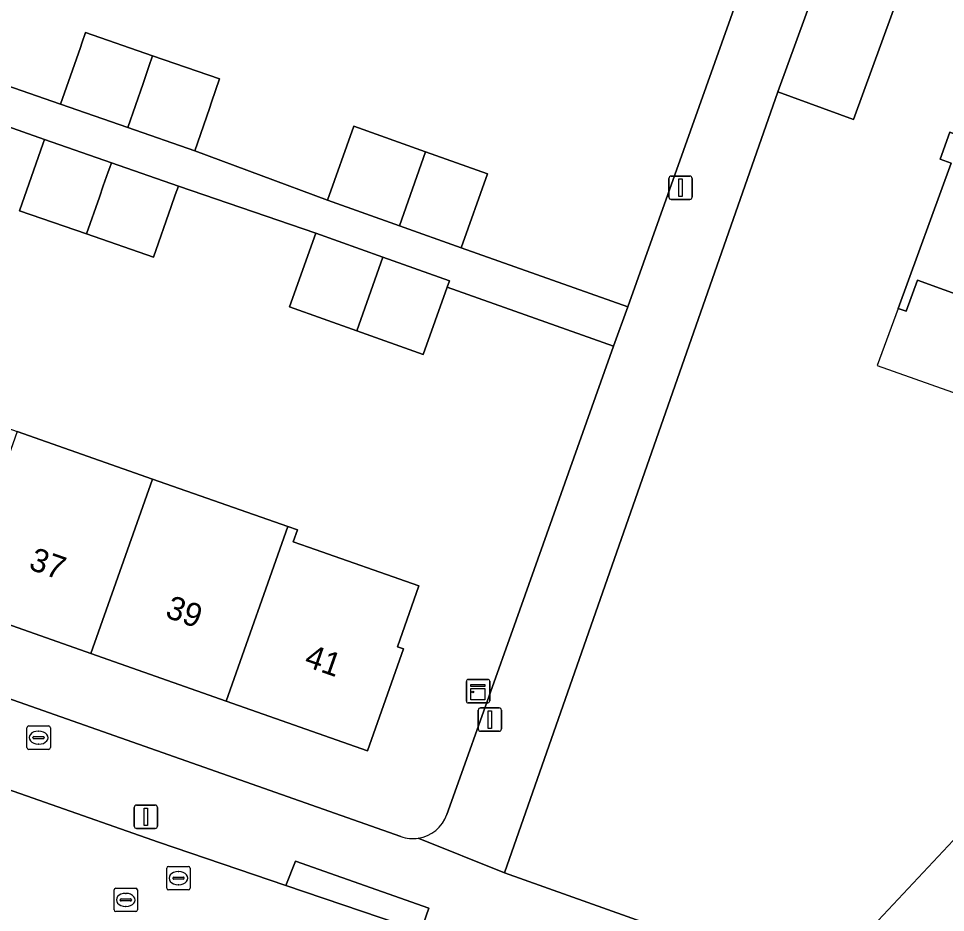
# Model space of a CAD drawing. Extents: x 163266 to 164362, y 381528 to 382286.
# Drawn here: x 163804.78 to 163844.41, y 381775.16 to 381813.39 of the extents above; entities that cross this region are included whole.
import ezdxf

# ---------------------------------------------------------------- set-up
doc = ezdxf.new("R2010")
doc.units = 0
for name, color, linetype in [('IMGEO_Brandkraan', 7, 'Continuous'), ('IMGEO_Erf', 7, 'Continuous'), ('IMGEO_Groenvoorziening', 7, 'Continuous'), ('IMGEO_Kast', 7, 'Continuous'), ('IMGEO_Lichtmast', 7, 'Continuous'), ('IMGEO_Pand', 7, 'Continuous'), ('IMGEO_Pand_nummerreeks', 7, 'Continuous'), ('IMGEO_Pand_overbouw', 7, 'Continuous'), ('IMGEO_Rijbaan_lokaal_open', 7, 'Continuous'), ('IMGEO_Rioolput', 7, 'Continuous'), ('IMGEO_Voetpad_open', 7, 'Continuous')]:
    doc.layers.add(name, color=color, linetype=linetype)

msp = doc.modelspace()

# ---------------------------------------------------------------- linework, layer by layer
at = {"layer": 'IMGEO_Brandkraan'}
for p, q in [((163805.142, 381782.214), (163805.142, 381783.066)), ((163805.217, 381783.14), (163806.069, 381783.14)), ((163805.63, 381782.92), (163805.655, 381782.92)), ((163806.143, 381783.066), (163806.143, 381782.214)), ((163805.401, 381782.634), (163805.401, 381782.646)), ((163805.839, 381782.597), (163805.441, 381782.597)), ((163805.444, 381782.683), (163805.842, 381782.683)), ((163805.885, 381782.646), (163805.885, 381782.634)), ((163806.069, 381782.14), (163805.217, 381782.14)), ((163805.653, 381782.36), (163805.628, 381782.36))]:
    msp.add_line(p, q, dxfattribs=at)
for points in [[(163805.142, 381782.214), (163805.142, 381783.066)], [(163805.217, 381783.14), (163806.069, 381783.14)], [(163806.143, 381783.066), (163806.143, 381782.214)], [(163806.069, 381782.14), (163805.217, 381782.14)]]:
    msp.add_lwpolyline(points, dxfattribs=at)
for centre, radius, start, end in [((163805.219, 381783.064), 0.0765, 91.552, 178.448), ((163805.219, 381783.064), 0.0765, 91.552, 178.448), ((163806.067, 381783.064), 0.0765, 1.552, 88.448), ((163806.067, 381783.064), 0.0765, 1.552, 88.448), ((163805.441, 381782.643), 0.0403, 85.8775, 175.7526), ((163805.438, 381782.633), 0.0366, 178.938, 274.7102), ((163805.842, 381782.64), 0.043, 264.8664, 352.4533), ((163805.846, 381782.645), 0.0386, 1.7309, 96.639), ((163805.219, 381782.216), 0.0765, 181.552, 268.448), ((163805.219, 381782.216), 0.0765, 181.552, 268.448), ((163806.067, 381782.216), 0.0765, 271.552, 358.448), ((163806.067, 381782.216), 0.0765, 271.552, 358.448)]:
    msp.add_arc(centre, radius, start, end, dxfattribs=at)
for centre, major_axis, ratio, start_param, end_param in [((163805.629, 381782.64), (-0.387, 0.002), 0.722429, 4.712389, 7.853982), ((163805.654, 381782.64), (-0.39, 0.002), 0.717154, 1.570796, 4.712389)]:
    msp.add_ellipse(centre, major_axis=major_axis, ratio=ratio, start_param=start_param, end_param=end_param, dxfattribs=at)
at = {"layer": 'IMGEO_Erf'}
for points in [[(163870.142, 381820.239), (163868.584, 381818.998), (163862.223, 381814.784), (163844.697, 381820.821), (163841.425, 381821.949), (163840.49, 381819.175), (163843.72, 381818.001), (163840.476, 381809.078), (163837.246, 381810.252), (163825.558, 381776.861), (163838.968, 381772.083), (163846.023, 381779.611), (163846.214, 381780.09), (163981.759, 381896.51)], [(163800.621, 381811.792), (163806.584, 381809.723), (163807.426, 381812.147), (163807.494, 381812.342), (163807.652, 381812.795), (163810.515, 381811.8), (163813.379, 381810.806), (163813.037, 381809.821), (163812.943, 381809.548), (163812.313, 381807.735), (163817.989, 381805.627), (163819.112, 381808.782), (163822.186, 381807.688), (163824.831, 381806.746), (163823.708, 381803.591), (163830.823, 381801.068), (163837.898, 381820.939)], [(163830.22, 381799.374), (163823.108, 381801.906), (163822.081, 381799.021), (163819.239, 381800.033), (163816.362, 381801.057), (163817.485, 381804.213), (163811.615, 381806.229), (163811.483, 381805.849), (163811.313, 381805.36), (163810.558, 381803.185), (163807.694, 381804.18), (163804.83, 381805.175), (163805.633, 381807.488), (163805.817, 381808.017), (163805.887, 381808.218), (163800.078, 381810.276)], [(163823.091, 381779.35), (163823.577, 381780.714), (163826.051, 381787.665), (163830.22, 381799.374)], [(163789.253, 381789.626), (163821.122, 381778.41)]]:
    msp.add_lwpolyline(points, dxfattribs=at)
for points in [[(163850.495, 381808.192), (163850.341, 381807.769), (163857.72, 381805.087), (163857.893, 381805.563), (163858.214, 381805.446), (163857.362, 381803.102), (163857.863, 381802.92), (163857.44, 381801.757), (163856.99, 381801.921), (163854.999, 381796.441), (163849.415, 381798.471), (163849.891, 381799.782), (163843.214, 381802.209), (163842.728, 381800.873), (163842.386, 381800.997), (163844.643, 381807.207), (163844.173, 381807.378), (163844.59, 381808.526), (163845.076, 381808.349), (163845.658, 381809.949)], [(163810.505, 381793.699), (163816.29, 381791.665), (163816.701, 381791.52), (163816.524, 381791.016), (163817.181, 381790.785), (163821.897, 381789.126), (163820.984, 381786.53), (163821.242, 381786.439), (163819.707, 381782.075), (163813.66, 381784.202), (163807.875, 381786.237), (163802.09, 381788.272), (163796.306, 381790.307), (163790.526, 381792.34), (163792.185, 381797.057), (163793.151, 381799.803), (163798.936, 381797.768), (163804.72, 381795.734)]]:
    msp.add_lwpolyline(points, close=True, dxfattribs=at)
for centre, radius, start, end in [((163821.635, 381779.868), 1.546, 278.7591, 340.4353), ((163821.636, 381779.873), 1.551, 250.6385, 278.6689)]:
    msp.add_arc(centre, radius, start, end, dxfattribs=at)
at = {"layer": 'IMGEO_Groenvoorziening'}
msp.add_lwpolyline([(163849.537, 381774.989), (163847.227, 381777.818), (163846.291, 381778.92), (163846.023, 381779.611), (163838.968, 381772.083), (163843.096, 381770.612), (163844.113, 381770.197), (163845.182, 381771.143), (163846.052, 381771.894)], close=True, dxfattribs=at)
at = {"layer": 'IMGEO_Kast'}
for p, q in [((163823.925, 381784.204), (163823.925, 381785.045)), ((163823.925, 381785.045), (163823.925, 381784.204)), ((163824, 381785.129), (163824.841, 381785.129)), ((163824.841, 381785.129), (163824, 381785.129)), ((163824.925, 381785.054), (163824.925, 381784.213)), ((163824.925, 381784.213), (163824.925, 381785.054)), ((163824.85, 381784.129), (163824.009, 381784.129)), ((163824.009, 381784.129), (163824.85, 381784.129))]:
    msp.add_line(p, q, dxfattribs=at)
for points in [[(163824.12, 381784.919), (163824.72, 381784.919), (163824.72, 381784.834), (163824.12, 381784.834), (163824.12, 381784.919)], [(163824.12, 381784.744), (163824.72, 381784.744), (163824.72, 381784.255), (163824.12, 381784.255), (163824.12, 381784.744)]]:
    msp.add_lwpolyline(points, dxfattribs=at)
msp.add_circle((163824.204, 381784.593), 0.0377, dxfattribs=at)
for centre, start, end in [((163824.003, 381785.051), 92.4484, 184.2845), ((163824.003, 381785.051), 92.4484, 184.2845), ((163824.847, 381785.051), 2.4484, 94.2845), ((163824.847, 381785.051), 2.4484, 94.2845), ((163824.003, 381784.207), 182.4484, 274.2845), ((163824.003, 381784.207), 182.4484, 274.2845), ((163824.847, 381784.207), 272.4484, 4.2845), ((163824.847, 381784.207), 272.4484, 4.2845)]:
    msp.add_arc(centre, 0.0779, start, end, dxfattribs=at)
at = {"layer": 'IMGEO_Lichtmast'}
for p, q in [((163832.686, 381806.656), (163833.476, 381806.656)), ((163833.476, 381806.656), (163832.686, 381806.656)), ((163832.586, 381805.756), (163832.586, 381806.556)), ((163832.586, 381806.556), (163832.586, 381805.756)), ((163833.576, 381806.556), (163833.576, 381805.756)), ((163833.576, 381805.756), (163833.576, 381806.556)), ((163833.476, 381805.656), (163832.686, 381805.656)), ((163832.686, 381805.656), (163833.476, 381805.656)), ((163824.435, 381783.011), (163824.435, 381783.811)), ((163824.435, 381783.811), (163824.435, 381783.011)), ((163824.535, 381783.911), (163825.325, 381783.911)), ((163825.325, 381783.911), (163824.535, 381783.911)), ((163825.425, 381783.811), (163825.425, 381783.011)), ((163825.425, 381783.011), (163825.425, 381783.811)), ((163825.325, 381782.911), (163824.535, 381782.911)), ((163824.535, 381782.911), (163825.325, 381782.911)), ((163809.831, 381779.757), (163810.621, 381779.757)), ((163810.621, 381779.757), (163809.831, 381779.757)), ((163809.731, 381778.857), (163809.731, 381779.657)), ((163809.731, 381779.657), (163809.731, 381778.857)), ((163810.721, 381779.657), (163810.721, 381778.857)), ((163810.721, 381778.857), (163810.721, 381779.657)), ((163810.621, 381778.757), (163809.831, 381778.757)), ((163809.831, 381778.757), (163810.621, 381778.757))]:
    msp.add_line(p, q, dxfattribs=at)
for points in [[(163833.006, 381806.531), (163833.156, 381806.531), (163833.156, 381805.781), (163833.006, 381805.781), (163833.006, 381806.531)], [(163824.855, 381783.786), (163825.005, 381783.786), (163825.005, 381783.036), (163824.855, 381783.036), (163824.855, 381783.786)], [(163810.151, 381779.632), (163810.301, 381779.632), (163810.301, 381778.882), (163810.151, 381778.882), (163810.151, 381779.632)]]:
    msp.add_lwpolyline(points, dxfattribs=at)
for centre, start, end in [((163832.686, 381806.556), 90, 180), ((163832.686, 381806.556), 90, 180), ((163833.476, 381806.556), 0, 90), ((163833.476, 381806.556), 360, 90), ((163832.686, 381805.756), 180, 270), ((163832.686, 381805.756), 180, 270), ((163833.476, 381805.756), 270, 0), ((163833.476, 381805.756), 270, 0), ((163824.535, 381783.811), 90, 180), ((163824.535, 381783.811), 90, 180), ((163825.325, 381783.811), 0, 90), ((163825.325, 381783.811), 360, 90), ((163824.535, 381783.011), 180, 270), ((163824.535, 381783.011), 180, 270), ((163825.325, 381783.011), 270, 0), ((163825.325, 381783.011), 270, 0), ((163809.831, 381779.657), 90, 180), ((163809.831, 381779.657), 90, 180), ((163810.621, 381779.657), 0, 90), ((163810.621, 381779.657), 360, 90), ((163809.831, 381778.857), 180, 270), ((163809.831, 381778.857), 180, 270), ((163810.621, 381778.857), 270, 0), ((163810.621, 381778.857), 270, 0)]:
    msp.add_arc(centre, 0.1, start, end, dxfattribs=at)
at = {"layer": 'IMGEO_Pand'}
for points in [[(163837.246, 381810.252), (163840.476, 381809.078), (163843.72, 381818.001), (163840.49, 381819.175)], [(163810.515, 381811.8), (163807.652, 381812.795), (163807.494, 381812.342), (163807.426, 381812.147), (163806.584, 381809.723), (163809.449, 381808.729), (163810.105, 381810.618), (163810.22, 381810.951), (163810.358, 381811.347)], [(163810.515, 381811.8), (163810.358, 381811.347), (163810.22, 381810.951), (163810.105, 381810.618), (163809.449, 381808.729), (163812.313, 381807.735), (163812.943, 381809.548), (163813.037, 381809.821), (163813.379, 381810.806)], [(163854.999, 381796.441), (163856.99, 381801.921), (163857.44, 381801.757), (163857.863, 381802.92), (163857.362, 381803.102), (163858.214, 381805.446), (163857.893, 381805.563), (163857.72, 381805.087), (163850.341, 381807.769), (163850.495, 381808.192), (163845.658, 381809.949), (163845.076, 381808.349), (163844.59, 381808.526), (163844.173, 381807.378), (163844.643, 381807.207), (163842.386, 381800.997), (163842.728, 381800.873), (163843.214, 381802.209), (163849.891, 381799.782), (163849.415, 381798.471)], [(163821.072, 381804.529), (163822.186, 381807.688), (163819.112, 381808.782), (163817.989, 381805.627)], [(163808.751, 381807.223), (163805.887, 381808.218), (163805.817, 381808.017), (163805.633, 381807.488), (163804.83, 381805.175), (163807.694, 381804.18), (163808.24, 381805.752), (163808.408, 381806.237), (163808.615, 381806.833), (163808.681, 381807.023)], [(163821.072, 381804.529), (163823.708, 381803.591), (163824.831, 381806.746), (163822.186, 381807.688)], [(163811.615, 381806.229), (163808.751, 381807.223), (163808.681, 381807.023), (163808.615, 381806.833), (163808.408, 381806.237), (163808.24, 381805.752), (163807.694, 381804.18), (163810.558, 381803.185), (163811.313, 381805.36), (163811.483, 381805.849)], [(163820.352, 381803.192), (163817.485, 381804.213), (163816.362, 381801.057), (163819.239, 381800.033)], [(163823.108, 381801.906), (163823.204, 381802.177), (163820.352, 381803.192), (163819.239, 381800.033), (163822.081, 381799.021)], [(163804.72, 381795.734), (163802.09, 381788.272), (163807.875, 381786.237), (163810.505, 381793.699)], [(163813.66, 381784.202), (163816.29, 381791.665), (163810.505, 381793.699), (163807.875, 381786.237)], [(163813.66, 381784.202), (163819.707, 381782.075), (163821.242, 381786.439), (163820.984, 381786.53), (163821.897, 381789.126), (163817.181, 381790.785), (163816.524, 381791.016), (163816.701, 381791.52), (163816.29, 381791.665)]]:
    msp.add_lwpolyline(points, close=True, dxfattribs=at)
at = {"layer": 'IMGEO_Pand_overbouw'}
msp.add_lwpolyline([(163842.386, 381800.997), (163841.483, 381798.56), (163854.131, 381794.08), (163854.999, 381796.441), (163849.415, 381798.471), (163849.891, 381799.782), (163843.214, 381802.209), (163842.728, 381800.873)], close=True, dxfattribs=at)
at = {"layer": 'IMGEO_Rijbaan_lokaal_open'}
msp.add_lwpolyline([(163832.755, 381770.426), (163821.983, 381774.359), (163821.874, 381774.396), (163816.213, 381776.322), (163810.767, 381778.175), (163800.522, 381781.766)], dxfattribs=at)
at = {"layer": 'IMGEO_Rioolput'}
for p, q in [((163811.119, 381776.206), (163811.119, 381777.058)), ((163811.194, 381777.132), (163812.046, 381777.132)), ((163812.12, 381777.058), (163812.12, 381776.206)), ((163811.378, 381776.626), (163811.378, 381776.638)), ((163811.816, 381776.589), (163811.418, 381776.589)), ((163811.421, 381776.675), (163811.819, 381776.675)), ((163811.607, 381776.912), (163811.632, 381776.912)), ((163811.862, 381776.638), (163811.862, 381776.626)), ((163808.941, 381776.2), (163809.793, 381776.2)), ((163811.63, 381776.352), (163811.605, 381776.352)), ((163808.866, 381775.274), (163808.866, 381776.126)), ((163809.168, 381775.743), (163809.566, 381775.743)), ((163809.354, 381775.98), (163809.379, 381775.98)), ((163809.867, 381776.126), (163809.867, 381775.274)), ((163812.046, 381776.132), (163811.194, 381776.132)), ((163809.125, 381775.694), (163809.125, 381775.706)), ((163809.563, 381775.657), (163809.165, 381775.657)), ((163809.377, 381775.42), (163809.352, 381775.42)), ((163809.609, 381775.706), (163809.609, 381775.694)), ((163809.793, 381775.2), (163808.941, 381775.2))]:
    msp.add_line(p, q, dxfattribs=at)
for points in [[(163811.119, 381776.206), (163811.119, 381777.058)], [(163811.194, 381777.132), (163812.046, 381777.132)], [(163812.12, 381777.058), (163812.12, 381776.206)], [(163808.941, 381776.2), (163809.793, 381776.2)], [(163808.866, 381775.274), (163808.866, 381776.126)], [(163809.867, 381776.126), (163809.867, 381775.274)], [(163812.046, 381776.132), (163811.194, 381776.132)], [(163809.793, 381775.2), (163808.941, 381775.2)]]:
    msp.add_lwpolyline(points, dxfattribs=at)
for centre, radius, start, end in [((163811.196, 381777.056), 0.0765, 91.552, 178.448), ((163811.196, 381777.056), 0.0765, 91.552, 178.448), ((163812.044, 381777.056), 0.0765, 1.552, 88.448), ((163812.044, 381777.056), 0.0765, 1.552, 88.448), ((163811.418, 381776.635), 0.0403, 85.8775, 175.7526), ((163811.415, 381776.625), 0.0366, 178.938, 274.7102), ((163811.819, 381776.632), 0.043, 264.8664, 352.4533), ((163811.823, 381776.637), 0.0386, 1.7309, 96.639), ((163808.943, 381776.124), 0.0765, 91.552, 178.448), ((163808.943, 381776.124), 0.0765, 91.552, 178.448), ((163809.791, 381776.124), 0.0765, 1.552, 88.448), ((163809.791, 381776.124), 0.0765, 1.552, 88.448), ((163811.196, 381776.208), 0.0765, 181.552, 268.448), ((163811.196, 381776.208), 0.0765, 181.552, 268.448), ((163812.044, 381776.208), 0.0765, 271.552, 358.448), ((163812.044, 381776.208), 0.0765, 271.552, 358.448), ((163809.165, 381775.703), 0.0403, 85.8775, 175.7526), ((163809.57, 381775.705), 0.0386, 1.7309, 96.639), ((163809.162, 381775.693), 0.0366, 178.938, 274.7102), ((163809.566, 381775.7), 0.043, 264.8664, 352.4533), ((163808.943, 381775.276), 0.0765, 181.552, 268.448), ((163808.943, 381775.276), 0.0765, 181.552, 268.448), ((163809.791, 381775.276), 0.0765, 271.552, 358.448), ((163809.791, 381775.276), 0.0765, 271.552, 358.448)]:
    msp.add_arc(centre, radius, start, end, dxfattribs=at)
for centre, major_axis, ratio, start_param, end_param in [((163811.606, 381776.632), (-0.387, 0.002), 0.722429, 4.712389, 7.853982), ((163811.631, 381776.632), (-0.39, 0.002), 0.717154, 1.570796, 4.712389), ((163809.353, 381775.7), (-0.387, 0.002), 0.722429, 4.712389, 7.853982), ((163809.378, 381775.7), (-0.39, 0.002), 0.717154, 1.570796, 4.712389)]:
    msp.add_ellipse(centre, major_axis=major_axis, ratio=ratio, start_param=start_param, end_param=end_param, dxfattribs=at)
at = {"layer": 'IMGEO_Voetpad_open'}
for points in [[(163686.577, 381826.945), (163685.646, 381824.121), (163685.076, 381822.394), (163704.639, 381815.509), (163720.044, 381810.112), (163726.041, 381807.998), (163740.853, 381802.813), (163758.246, 381796.703), (163758.267, 381796.696), (163759.961, 381796.019), (163778.368, 381789.58), (163800.522, 381781.766), (163810.767, 381778.175), (163816.213, 381776.322), (163816.626, 381777.354), (163822.318, 381775.342), (163821.983, 381774.359), (163832.755, 381770.426)], [(163821.122, 381778.41), (163789.253, 381789.626), (163787.244, 381790.333), (163728.773, 381810.911), (163727.155, 381811.48), (163687.737, 381825.353)], [(163837.246, 381810.252), (163840.49, 381819.175), (163841.425, 381821.949), (163837.992, 381821.299)], [(163837.898, 381820.939), (163830.823, 381801.068), (163830.22, 381799.374), (163826.051, 381787.665), (163823.577, 381780.714), (163823.091, 381779.35)], [(163800.078, 381810.276), (163805.887, 381808.218), (163808.751, 381807.223), (163811.615, 381806.229), (163817.485, 381804.213), (163820.352, 381803.192), (163823.204, 381802.177), (163823.108, 381801.906), (163830.22, 381799.374), (163830.823, 381801.068), (163823.708, 381803.591), (163821.072, 381804.529), (163817.989, 381805.627), (163812.313, 381807.735), (163809.449, 381808.729), (163806.584, 381809.723), (163800.621, 381811.792)], [(163821.87, 381778.34), (163825.558, 381776.861), (163837.246, 381810.252)], [(163843.007, 381769.261), (163844.113, 381770.197), (163843.096, 381770.612), (163838.968, 381772.083), (163825.558, 381776.861), (163821.87, 381778.34)]]:
    msp.add_lwpolyline(points, dxfattribs=at)
msp.add_lwpolyline([(163816.213, 381776.322), (163821.874, 381774.396), (163821.983, 381774.359), (163822.318, 381775.342), (163816.626, 381777.354)], close=True, dxfattribs=at)
for centre, radius, start, end in [((163821.635, 381779.868), 1.546, 278.7591, 340.4353), ((163821.636, 381779.873), 1.551, 250.6385, 278.6689)]:
    msp.add_arc(centre, radius, start, end, dxfattribs=at)

# ---------------------------------------------------------------- texts
at = {"layer": 'IMGEO_Pand_nummerreeks'}
for s, p in [('37', (163805.173, 381789.859)), ('39', (163811.009, 381787.806)), ('41', (163816.952, 381785.715))]:
    msp.add_text(s, height=1, rotation=340.6197, dxfattribs=at).set_placement(p)

doc.saveas('drawing.dxf')
